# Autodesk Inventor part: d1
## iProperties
Created: 2002-02
Part Number: d1
Document SubType Name: ﾓﾃﾞﾘﾝｸﾞ
Designer: Administrator
Control State: 0
Master: False
Checked Out: False
Shininess: 64.0
Length Units: 11269
Angle Units: 11279
Time Units: 11290
Mass Units: 11284
Length Display Precision: 2
Angle Display Precision: 1
Density: 0.0
Volumn: 0.0
Area: 0.0
PropertySet Name: Model Information
Author: Administrator
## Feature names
1. 押し出し4 [Extrusion]
